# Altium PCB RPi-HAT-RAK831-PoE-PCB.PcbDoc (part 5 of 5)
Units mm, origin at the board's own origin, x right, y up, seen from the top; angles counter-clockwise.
Board outline 65 x 56 mm, 2 copper layers (Top Layer, Bottom Layer); 9 components, 14 nets, 9110 pads, 249 vias.
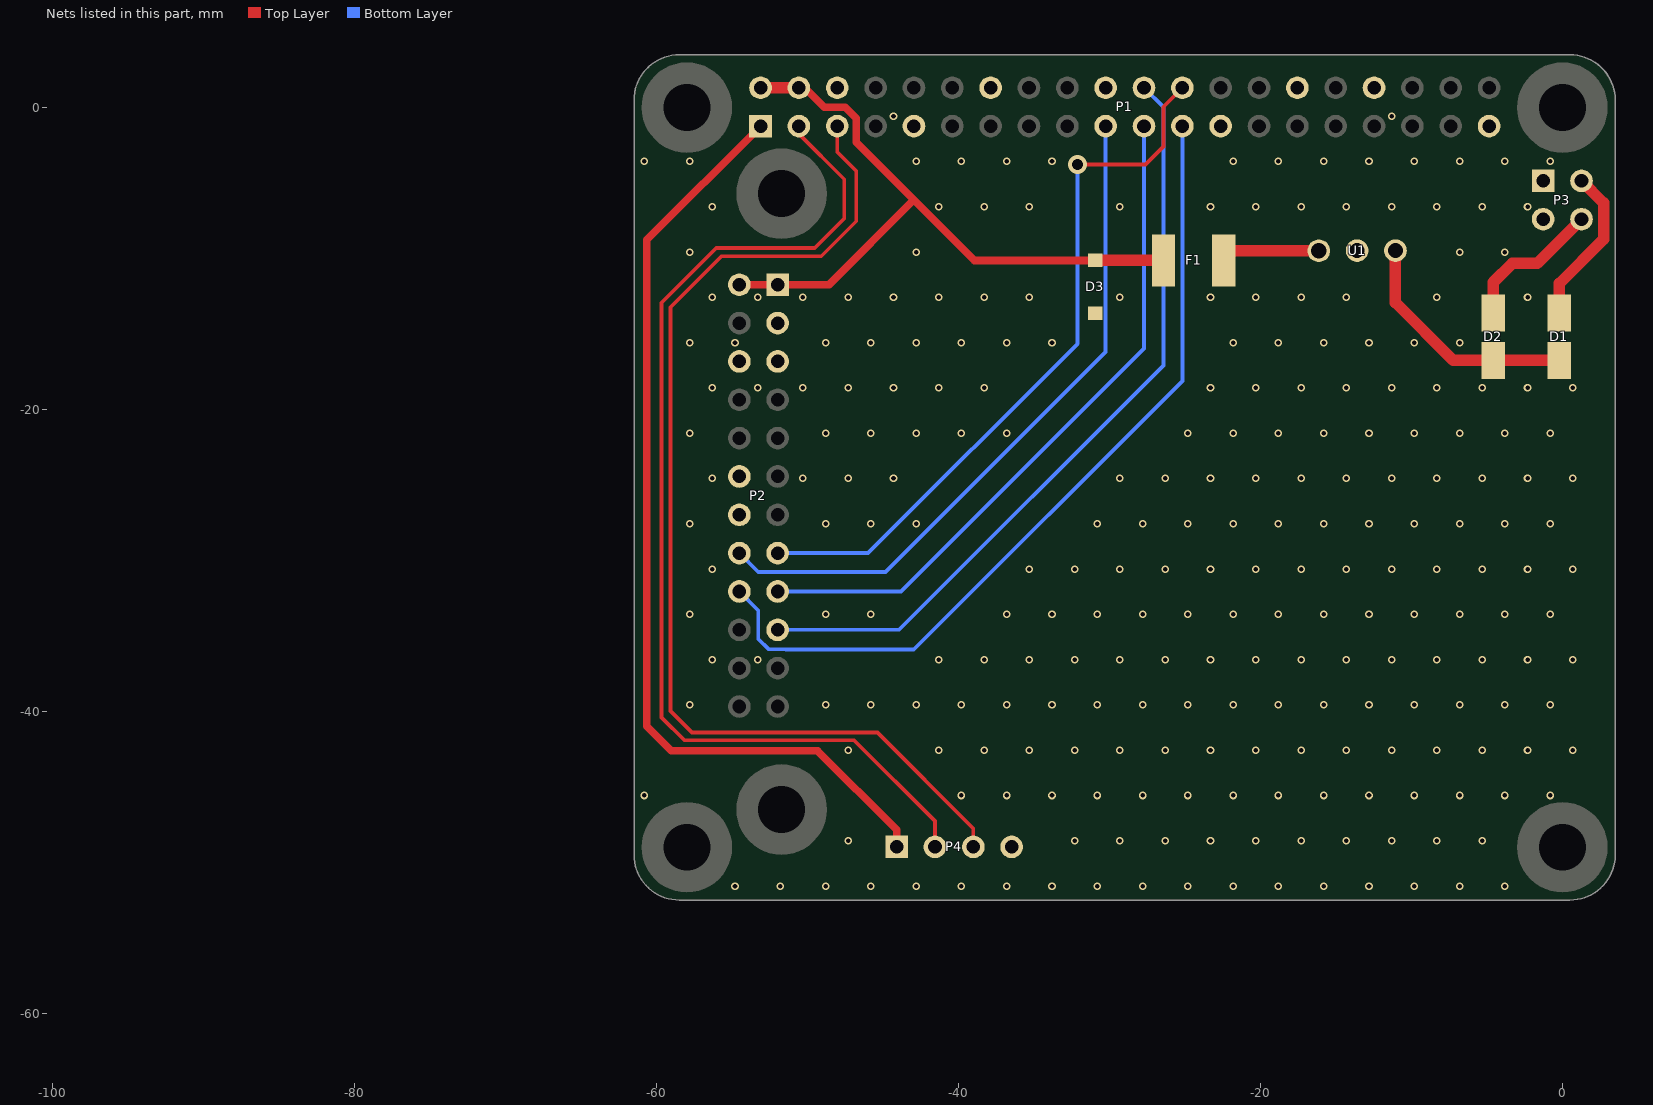
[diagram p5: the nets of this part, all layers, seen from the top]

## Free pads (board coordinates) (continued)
  round 0.025 on Top Overlay: 1(-16.322,-45.815) 1(-16.322,-45.79) 1(-16.322,-45.764) 1(-16.322,-44.621) 1(-16.322,-44.596) 1(-16.322,-44.571) 1(-16.297,-45.866) 1(-16.297,-45.841) 1(-16.297,-44.545) 1(-16.297,-44.52) 1(-16.297,-44.494) 1(-16.271,-45.917) 1(-16.271,-45.891) 1(-16.271,-44.469) 1(-16.271,-44.444) 1(-16.246,-45.968) 1(-16.246,-45.942) 1(-16.246,-44.418) 1(-16.22,-45.993) 1(-16.22,-44.393) 1(-16.22,-44.367) 1(-16.195,-46.044) 1(-16.195,-46.018) 1(-16.195,-44.342) 1(-16.195,-44.317) 1(-16.17,-46.069) 1(-16.17,-44.291) 1(-16.144,-46.095) 1(-16.144,-44.266) 1(-16.144,-44.24) 1(-16.119,-46.145) 1(-16.119,-46.12) 1(-16.119,-44.215) 1(-16.093,-46.171) 1(-16.093,-44.19) 1(-16.068,-46.196) 1(-16.068,-44.164) 1(-16.043,-46.222) 1(-16.043,-44.139) 1(-16.017,-46.247) 1(-16.017,-44.113) 1(-15.992,-44.088) 1(-15.966,-46.272) 1(-15.966,-44.063) 1(-15.941,-46.298) 1(-15.941,-44.037) 1(-15.916,-46.323) 1(-15.916,-44.012) 1(-15.89,-43.986) 1(-15.865,-46.349) 1(-15.839,-46.374) 1(-15.839,-43.961) 1(-15.814,-43.936) 1(-15.789,-46.399) 1(-15.763,-43.91) 1(-15.738,-46.425) 1(-15.738,-43.885) 1(-15.687,-46.45) 1(-15.687,-43.859) 1(-15.636,-43.834) 1(-15.611,-46.476) 1(-15.585,-45.51) 1(-15.585,-45.485) 1(-15.585,-45.46) 1(-15.585,-45.434) 1(-15.585,-45.409) 1(-15.585,-44.875) 1(-15.585,-44.85) 1(-15.585,-44.825) 1(-15.585,-44.799) 1(-15.56,-45.612) 1(-15.56,-45.587) 1(-15.56,-45.561) 1(-15.56,-45.536) 1(-15.56,-44.774) 1(-15.56,-44.748) 1(-15.56,-44.723) 1(-15.56,-44.698) 1(-15.56,-43.809) 1(-15.535,-46.501) 1(-15.535,-45.663) 1(-15.535,-45.637) 1(-15.535,-44.672) 1(-15.535,-44.647) 1(-15.509,-45.714) 1(-15.509,-45.688) 1(-15.509,-44.621) 1(-15.509,-44.596) 1(-15.484,-45.764) 1(-15.484,-45.739) 1(-15.484,-44.571) 1(-15.484,-44.545) 1(-15.484,-43.783) 1(-15.458,-45.79) 1(-15.458,-44.52) 1(-15.458,-44.494) 1(-15.433,-46.526) 1(-15.433,-45.815) 1(-15.433,-44.469) 1(-15.408,-45.841) 1(-15.408,-44.444) 1(-15.408,-43.758) 1(-15.382,-45.866) 1(-15.382,-44.418) 1(-15.357,-45.891) 1(-15.357,-44.393) 1(-15.331,-44.367) 1(-15.306,-45.917) 1(-15.306,-44.342) 1(-15.281,-46.552) 1(-15.281,-45.942) 1(-15.255,-44.317) 1(-15.255,-43.732) 1(-15.204,-45.968) 1(-15.204,-44.291) 1(-15.128,-45.993) 1(-15.128,-44.266) 1(-15.001,-46.018) 1(-14.95,-44.266) 1(-14.849,-44.291) 1(-14.823,-43.732) 1(-14.798,-44.317) 1(-14.773,-44.342) 1(-14.747,-44.367) 1(-14.722,-46.552) 1(-14.722,-44.393) 1(-14.696,-44.418) 1(-14.671,-44.469) 1(-14.671,-44.444) 1(-14.671,-43.758) 1(-14.646,-46.018) 1(-14.646,-44.52) 1(-14.646,-44.494) 1(-14.62,-44.596) 1(-14.62,-44.571) 1(-14.62,-44.545) 1(-14.595,-44.723) 1(-14.595,-44.698) 1(-14.595,-44.672) 1(-14.595,-44.647) 1(-14.595,-44.621) 1(-14.569,-44.875) 1(-14.569,-44.85) 1(-14.569,-44.825) 1(-14.569,-44.799) 1(-14.569,-44.774) 1(-14.569,-44.748) 1(-14.569,-43.783) 1(-14.519,-46.526) 1(-14.519,-45.993) 1(-14.519,-43.809) 1(-14.442,-43.834) 1(-14.417,-45.968) 1(-14.392,-46.501) 1(-14.392,-43.859) 1(-14.341,-45.942) 1(-14.341,-43.885) 1(-14.315,-43.91) 1(-14.29,-46.476) 1(-14.265,-45.917) 1(-14.265,-43.936) 1(-14.239,-43.961) 1(-14.214,-46.45) 1(-14.214,-45.891) 1(-14.214,-43.986) 1(-14.188,-44.012) 1(-14.163,-46.425) 1(-14.163,-45.866) 1(-14.163,-44.037) 1(-14.138,-44.063) 1(-14.112,-45.841) 1(-14.112,-44.088) 1(-14.087,-46.399) 1(-14.087,-45.815) 1(-14.087,-44.113) 1(-14.061,-44.139) 1(-14.036,-46.374) 1(-14.036,-46.349) 1(-14.036,-46.323) 1(-14.036,-46.298) 1(-14.036,-46.272) 1(-14.036,-46.247) 1(-14.036,-46.222) 1(-14.036,-46.196) 1(-14.036,-46.171) 1(-14.036,-46.145) 1(-14.036,-46.12) 1(-14.036,-46.095) 1(-14.036,-46.069) 1(-14.036,-46.044) 1(-14.036,-46.018) 1(-14.036,-45.993) 1(-14.036,-45.968) 1(-14.036,-45.942) 1(-14.036,-45.917) 1(-14.036,-45.891) 1(-14.036,-45.866) 1(-14.036,-45.841) 1(-14.036,-45.815) 1(-14.036,-44.19) 1(-14.036,-44.164) 1(-14.011,-44.215) 1(-13.985,-44.266) 1(-13.985,-44.24) 1(-13.96,-44.317) 1(-13.96,-44.291) 1(-13.934,-44.367) 1(-13.934,-44.342) 1(-13.909,-44.418) 1(-13.909,-44.393) 1(-13.884,-44.494) 1(-13.884,-44.469) 1(-13.884,-44.444) 1(-13.858,-44.571) 1(-13.858,-44.545) 1(-13.858,-44.52) 1(-13.833,-44.698) 1(-13.833,-44.672) 1(-13.833,-44.647) 1(-13.833,-44.621) 1(-13.833,-44.596) 1(-13.807,-44.901) 1(-13.807,-44.875) 1(-13.807,-44.85) 1(-13.807,-44.825) 1(-13.807,-44.799) 1(-13.807,-44.774) 1(-13.807,-44.748) 1(-13.807,-44.723) 1(-13.782,-45.383) 1(-13.782,-45.358) 1(-13.782,-45.333) 1(-13.782,-45.307) 1(-13.782,-45.282) 1(-13.782,-45.256) 1(-13.782,-45.231) 1(-13.782,-45.206) 1(-13.782,-45.18) 1(-13.782,-45.155) 1(-13.782,-45.129) 1(-13.782,-45.104) 1(-13.782,-45.079) 1(-13.782,-45.053) 1(-13.782,-45.028) 1(-13.782,-45.002) 1(-13.782,-44.977) 1(-13.782,-44.952) 1(-13.782,-44.926) 1(-13.63,-43.834) 1(-13.63,-43.809) 1(-13.63,-43.783) 1(-13.604,-43.91) 1(-13.604,-43.885) 1(-13.604,-43.859) 1(-13.579,-44.012) 1(-13.579,-43.986) 1(-13.579,-43.961) 1(-13.579,-43.936) 1(-13.553,-44.088) 1(-13.553,-44.063) 1(-13.553,-44.037) 1(-13.528,-44.19) 1(-13.528,-44.164) 1(-13.528,-44.139) 1(-13.528,-44.113) 1(-13.503,-44.266) 1(-13.503,-44.24) 1(-13.503,-44.215) 1(-13.477,-44.367) 1(-13.477,-44.342) 1(-13.477,-44.317) 1(-13.477,-44.291) 1(-13.452,-44.444) 1(-13.452,-44.418) 1(-13.452,-44.393) 1(-13.426,-44.545) 1(-13.426,-44.52) 1(-13.426,-44.494) 1(-13.426,-44.469) 1(-13.401,-44.621) 1(-13.401,-44.596) 1(-13.401,-44.571) 1(-13.376,-44.723) 1(-13.376,-44.698) 1(-13.376,-44.672) 1(-13.376,-44.647) 1(-13.35,-44.799) 1(-13.35,-44.774) 1(-13.35,-44.748) 1(-13.325,-44.901) 1(-13.325,-44.875) 1(-13.325,-44.85) 1(-13.325,-44.825) 1(-13.299,-44.977) 1(-13.299,-44.952) 1(-13.299,-44.926) 1(-13.274,-45.079) 1(-13.274,-45.053) 1(-13.274,-45.028) 1(-13.274,-45.002) 1(-13.249,-45.155) 1(-13.249,-45.129) 1(-13.249,-45.104) 1(-13.223,-45.256) 1(-13.223,-45.231) 1(-13.223,-45.206) 1(-13.223,-45.18) 1(-13.198,-45.333) 1(-13.198,-45.307) 1(-13.198,-45.282) 1(-13.172,-45.434) 1(-13.172,-45.409) 1(-13.172,-45.383) 1(-13.172,-45.358) 1(-13.147,-45.51) 1(-13.147,-45.485) 1(-13.147,-45.46) 1(-13.122,-45.612) 1(-13.122,-45.587) 1(-13.122,-45.561) 1(-13.122,-45.536) 1(-13.096,-45.688) 1(-13.096,-45.663) 1(-13.096,-45.637) 1(-13.071,-45.79) 1(-13.071,-45.764) 1(-13.071,-45.739) 1(-13.071,-45.714) 1(-13.045,-45.866) 1(-13.045,-45.841) 1(-13.045,-45.815) 1(-13.02,-45.942) 1(-13.02,-45.917) 1(-13.02,-45.891) 1(-12.995,-46.044) 1(-12.995,-46.018) 1(-12.995,-45.993) 1(-12.995,-45.968) 1(-12.969,-46.12) 1(-12.969,-46.095) 1(-12.969,-46.069) 1(-12.944,-46.222) 1(-12.944,-46.196) 1(-12.944,-46.171) 1(-12.944,-46.145) 1(-12.918,-46.298) 1(-12.918,-46.272) 1(-12.918,-46.247) 1(-12.893,-46.399) 1(-12.893,-46.374) 1(-12.893,-46.349) 1(-12.893,-46.323) 1(-12.868,-46.476) 1(-12.868,-46.45) 1(-12.868,-46.425) 1(-12.842,-46.501) 1(-12.766,-43.885) 1(-12.766,-43.859) 1(-12.766,-43.834) 1(-12.766,-43.809) 1(-12.766,-43.783) 1(-12.741,-43.986) 1(-12.741,-43.961) 1(-12.741,-43.936) 1(-12.741,-43.91) 1(-12.715,-44.113) 1(-12.715,-44.088) 1(-12.715,-44.063) 1(-12.715,-44.037) 1(-12.715,-44.012) 1(-12.69,-44.215) 1(-12.69,-44.19) 1(-12.69,-44.164) 1(-12.69,-44.139) 1(-12.664,-44.342) 1(-12.664,-44.317) 1(-12.664,-44.291) 1(-12.664,-44.266) 1(-12.664,-44.24) 1(-12.639,-44.444) 1(-12.639,-44.418) 1(-12.639,-44.393) 1(-12.639,-44.367) 1(-12.614,-44.571) 1(-12.614,-44.545) 1(-12.614,-44.52) 1(-12.614,-44.494) 1(-12.614,-44.469) 1(-12.588,-44.672) 1(-12.588,-44.647) 1(-12.588,-44.621) 1(-12.588,-44.596) 1(-12.563,-44.799) 1(-12.563,-44.774) 1(-12.563,-44.748) 1(-12.563,-44.723) 1(-12.563,-44.698) 1(-12.537,-44.901) 1(-12.537,-44.875) 1(-12.537,-44.85) 1(-12.537,-44.825) 1(-12.512,-45.028) 1(-12.512,-45.002) 1(-12.512,-44.977) 1(-12.512,-44.952) 1(-12.512,-44.926) 1(-12.487,-45.129) 1(-12.487,-45.104) 1(-12.487,-45.079) 1(-12.487,-45.053) 1(-12.461,-45.231) 1(-12.461,-45.206) 1(-12.461,-45.18) 1(-12.461,-45.155) 1(-12.436,-45.358) 1(-12.436,-45.333) 1(-12.436,-45.307) 1(-12.436,-45.282) 1(-12.436,-45.256) 1(-12.41,-45.46) 1(-12.41,-45.434) 1(-12.41,-45.409) 1(-12.41,-45.383) 1(-12.385,-45.587) 1(-12.385,-45.561) 1(-12.385,-45.536) 1(-12.385,-45.51) 1(-12.385,-45.485) 1(-12.36,-45.739) 1(-12.36,-45.714) 1(-12.36,-45.688) 1(-12.36,-45.663) 1(-12.36,-45.637) 1(-12.36,-45.612) 1(-12.334,-45.739) 1(-12.334,-45.714) 1(-12.334,-45.688) 1(-12.334,-45.663) 1(-12.334,-45.637) 1(-12.309,-45.612) 1(-12.309,-45.587) 1(-12.309,-45.561) 1(-12.309,-45.536) 1(-12.283,-45.51) 1(-12.283,-45.485) 1(-12.283,-45.46) 1(-12.283,-45.434) 1(-12.258,-45.409) 1(-12.258,-45.383) 1(-12.258,-45.358) 1(-12.233,-45.333) 1(-12.233,-45.307) 1(-12.233,-45.282) 1(-12.233,-45.256) 1(-12.207,-45.231) 1(-12.207,-45.206) 1(-12.207,-45.18) 1(-12.207,-45.155) 1(-12.182,-45.129) 1(-12.182,-45.104) 1(-12.182,-45.079) 1(-12.156,-45.053) 1(-12.156,-45.028) 1(-12.156,-45.002) 1(-12.156,-44.977) 1(-12.131,-44.952) 1(-12.131,-44.926) 1(-12.131,-44.901) 1(-12.131,-44.875) 1(-12.106,-44.85) 1(-12.106,-44.825) 1(-12.106,-44.799) 1(-12.08,-44.774) 1(-12.08,-44.748) 1(-12.08,-44.723) 1(-12.08,-44.698) 1(-12.055,-44.672) 1(-12.055,-44.647) 1(-12.055,-44.621) 1(-12.055,-44.596) 1(-12.029,-44.571) 1(-12.029,-44.545) 1(-12.029,-44.52) 1(-12.004,-44.494) 1(-12.004,-44.469) 1(-12.004,-44.444) 1(-12.004,-44.418) 1(-11.979,-46.501) 1(-11.979,-46.476) 1(-11.979,-44.393) 1(-11.979,-44.367) 1(-11.979,-44.342) 1(-11.979,-44.317) 1(-11.953,-46.45) 1(-11.953,-46.425) 1(-11.953,-46.399) 1(-11.953,-46.374) 1(-11.953,-44.291) 1(-11.953,-44.266) 1(-11.953,-44.24) 1(-11.928,-46.349) 1(-11.928,-46.323) 1(-11.928,-46.298) 1(-11.928,-44.215) 1(-11.928,-44.19) 1(-11.928,-44.164) 1(-11.928,-44.139) 1(-11.902,-46.272) 1(-11.902,-46.247) 1(-11.902,-46.222) 1(-11.902,-46.196) 1(-11.902,-44.113) 1(-11.902,-44.088) 1(-11.902,-44.063) 1(-11.902,-44.037) 1(-11.877,-46.171) 1(-11.877,-46.145) 1(-11.877,-46.12) 1(-11.877,-46.095) 1(-11.877,-44.012) 1(-11.877,-43.986) 1(-11.877,-43.961) 1(-11.852,-46.069) 1(-11.852,-46.044) 1(-11.852,-46.018) 1(-11.852,-43.936) 1(-11.852,-43.91) 1(-11.852,-43.885) 1(-11.852,-43.859) 1(-11.826,-45.993) 1(-11.826,-45.968) 1(-11.826,-45.942) 1(-11.826,-45.917) 1(-11.826,-43.834) 1(-11.826,-43.809) 1(-11.826,-43.783) 1(-11.801,-45.891) 1(-11.801,-45.866) 1(-11.801,-45.841) 1(-11.801,-45.815) 1(-11.775,-45.79) 1(-11.775,-45.764) 1(-11.775,-45.739) 1(-11.75,-45.714) 1(-11.75,-45.688) 1(-11.75,-45.663) 1(-11.75,-45.637) 1(-11.725,-45.612) 1(-11.725,-45.587) 1(-11.725,-45.561) 1(-11.725,-45.536) 1(-11.699,-45.51) 1(-11.699,-45.485) 1(-11.699,-45.46) 1(-11.674,-45.434) 1(-11.674,-45.409) 1(-11.674,-45.383) 1(-11.674,-45.358) 1(-11.648,-45.333) 1(-11.648,-45.307) 1(-11.648,-45.282) 1(-11.648,-45.256) 1(-11.623,-45.231) 1(-11.623,-45.206) 1(-11.623,-45.18) 1(-11.598,-45.155) 1(-11.598,-45.129) 1(-11.598,-45.104) 1(-11.598,-45.079) 1(-11.572,-45.053) 1(-11.572,-45.028) 1(-11.572,-45.002) 1(-11.572,-44.977) 1(-11.547,-44.952) 1(-11.547,-44.926) 1(-11.547,-44.901) 1(-11.521,-44.875) 1(-11.521,-44.85) 1(-11.521,-44.825) 1(-11.521,-44.799) 1(-11.521,-44.774) 1(-11.496,-44.748) 1(-11.496,-44.723) 1(-11.496,-44.698) 1(-11.471,-44.825) 1(-11.471,-44.799) 1(-11.471,-44.774) 1(-11.471,-44.748) 1(-11.471,-44.723) 1(-11.471,-44.698) 1(-11.445,-44.926) 1(-11.445,-44.901) 1(-11.445,-44.875) 1(-11.445,-44.85) 1(-11.42,-45.028) 1(-11.42,-45.002) 1(-11.42,-44.977) 1(-11.42,-44.952) 1(-11.394,-45.129) 1(-11.394,-45.104) 1(-11.394,-45.079) 1(-11.394,-45.053) 1(-11.369,-45.231) 1(-11.369,-45.206) 1(-11.369,-45.18) 1(-11.369,-45.155) 1(-11.344,-45.333) 1(-11.344,-45.307) 1(-11.344,-45.282) 1(-11.344,-45.256) 1(-11.318,-45.409) 1(-11.318,-45.383) 1(-11.318,-45.358) 1(-11.293,-45.51) 1(-11.293,-45.485) 1(-11.293,-45.46) 1(-11.293,-45.434) 1(-11.267,-45.612) 1(-11.267,-45.587) 1(-11.267,-45.561) 1(-11.267,-45.536) 1(-11.242,-45.714) 1(-11.242,-45.688) 1(-11.242,-45.663) 1(-11.242,-45.637) 1(-11.217,-45.815) 1(-11.217,-45.79) 1(-11.217,-45.764) 1(-11.217,-45.739) 1(-11.191,-45.917) 1(-11.191,-45.891) 1(-11.191,-45.866) 1(-11.191,-45.841) 1(-11.166,-46.018) 1(-11.166,-45.993) 1(-11.166,-45.968) 1(-11.166,-45.942) 1(-11.14,-46.12) 1(-11.14,-46.095) 1(-11.14,-46.069) 1(-11.14,-46.044) 1(-11.115,-46.222) 1(-11.115,-46.196) 1(-11.115,-46.171) 1(-11.115,-46.145) 1(-11.09,-46.323) 1(-11.09,-46.298) 1(-11.09,-46.272) 1(-11.09,-46.247) 1(-11.064,-46.425) 1(-11.064,-46.399) 1(-11.064,-46.374) 1(-11.064,-46.349) 1(-11.039,-46.501) 1(-11.039,-46.476) 1(-11.039,-46.45) 1(-11.013,-43.834) 1(-11.013,-43.809) 1(-11.013,-43.783) 1(-10.988,-43.961) 1(-10.988,-43.936) 1(-10.988,-43.91) 1(-10.988,-43.885) 1(-10.988,-43.859) 1(-10.963,-44.063) 1(-10.963,-44.037) 1(-10.963,-44.012) 1(-10.963,-43.986) 1(-10.937,-44.164) 1(-10.937,-44.139) 1(-10.937,-44.113) 1(-10.937,-44.088) 1(-10.912,-44.266) 1(-10.912,-44.24) 1(-10.912,-44.215) 1(-10.912,-44.19) 1(-10.886,-44.367) 1(-10.886,-44.342) 1(-10.886,-44.317) 1(-10.886,-44.291) 1(-10.861,-44.469) 1(-10.861,-44.444) 1(-10.861,-44.418) 1(-10.861,-44.393) 1(-10.836,-44.571) 1(-10.836,-44.545) 1(-10.836,-44.52) 1(-10.836,-44.494) 1(-10.81,-44.672) 1(-10.81,-44.647) 1(-10.81,-44.621) 1(-10.81,-44.596) 1(-10.785,-44.799) 1(-10.785,-44.774) 1(-10.785,-44.748) 1(-10.785,-44.723) 1(-10.785,-44.698) 1(-10.759,-44.901) 1(-10.759,-44.875) 1(-10.759,-44.85) 1(-10.759,-44.825) 1(-10.734,-45.002) 1(-10.734,-44.977) 1(-10.734,-44.952) 1(-10.734,-44.926) 1(-10.709,-45.104) 1(-10.709,-45.079) 1(-10.709,-45.053) 1(-10.709,-45.028) 1(-10.683,-45.206) 1(-10.683,-45.18) 1(-10.683,-45.155) 1(-10.683,-45.129) 1(-10.658,-45.307) 1(-10.658,-45.282) 1(-10.658,-45.256) 1(-10.658,-45.231) 1(-10.632,-45.409) 1(-10.632,-45.383) 1(-10.632,-45.358) 1(-10.632,-45.333) 1(-10.607,-45.536) 1(-10.607,-45.51) 1(-10.607,-45.485) 1(-10.607,-45.46) 1(-10.607,-45.434) 1(-10.582,-45.663) 1(-10.582,-45.637) 1(-10.582,-45.612) 1(-10.582,-45.587) 1(-10.582,-45.561) 1(-10.556,-45.688) 1(-10.531,-45.688) 1(-10.531,-45.663) 1(-10.531,-45.637) 1(-10.531,-45.612) 1(-10.531,-45.587) 1(-10.505,-45.561) 1(-10.505,-45.536) 1(-10.505,-45.51) 1(-10.505,-45.485) 1(-10.505,-45.46) 1(-10.48,-45.434) 1(-10.48,-45.409) 1(-10.48,-45.383) 1(-10.48,-45.358) 1(-10.48,-45.333) 1(-10.455,-45.307) 1(-10.455,-45.282) 1(-10.455,-45.256) 1(-10.455,-45.231) 1(-10.455,-45.206) 1(-10.429,-45.18) 1(-10.429,-45.155) 1(-10.429,-45.129) 1(-10.429,-45.104) 1(-10.404,-45.079) 1(-10.404,-45.053) 1(-10.404,-45.028) 1(-10.404,-45.002) 1(-10.404,-44.977) 1(-10.378,-44.952) 1(-10.378,-44.926) 1(-10.378,-44.901) 1(-10.378,-44.875) 1(-10.378,-44.85) 1(-10.353,-44.825) 1(-10.353,-44.799) 1(-10.353,-44.774) 1(-10.353,-44.748) 1(-10.353,-44.723) 1(-10.328,-44.698) 1(-10.328,-44.672) 1(-10.328,-44.647) 1(-10.328,-44.621) 1(-10.302,-44.596) 1(-10.302,-44.571) 1(-10.302,-44.545) 1(-10.302,-44.52) 1(-10.302,-44.494) 1(-10.277,-44.469) 1(-10.277,-44.444) 1(-10.277,-44.418) 1(-10.277,-44.393) 1(-10.277,-44.367) 1(-10.251,-44.342) 1(-10.251,-44.317) 1(-10.251,-44.291) 1(-10.251,-44.266) 1(-10.251,-44.24) 1(-10.226,-44.215) 1(-10.226,-44.19) 1(-10.226,-44.164) 1(-10.226,-44.139) 1(-10.201,-44.113) 1(-10.201,-44.088) 1(-10.201,-44.063) 1(-10.201,-44.037) 1(-10.201,-44.012) 1(-10.175,-43.986) 1(-10.175,-43.961) 1(-10.175,-43.936) 1(-10.175,-43.91) 1(-10.175,-43.885) 1(-10.15,-46.501) 1(-10.15,-46.476) 1(-10.15,-43.859) 1(-10.15,-43.834) 1(-10.15,-43.809) 1(-10.15,-43.783) 1(-10.124,-46.45) 1(-10.124,-46.425) 1(-10.124,-46.399) 1(-10.099,-46.374) 1(-10.099,-46.349) 1(-10.099,-46.323) 1(-10.099,-46.298) 1(-10.074,-46.272) 1(-10.074,-46.247) 1(-10.074,-46.222) 1(-10.048,-46.196) 1(-10.048,-46.171) 1(-10.048,-46.145) 1(-10.048,-46.12) 1(-10.023,-46.095) 1(-10.023,-46.069) 1(-10.023,-46.044) 1(-9.997,-46.018) 1(-9.997,-45.993) 1(-9.997,-45.968) 1(-9.997,-45.942) 1(-9.972,-45.917) 1(-9.972,-45.891) 1(-9.972,-45.866) 1(-9.947,-45.841) 1(-9.947,-45.815) 1(-9.947,-45.79) 1(-9.947,-45.764) 1(-9.921,-45.739) 1(-9.921,-45.714) 1(-9.921,-45.688) 1(-9.896,-45.663) 1(-9.896,-45.637) 1(-9.896,-45.612) 1(-9.896,-45.587) 1(-9.87,-45.561) 1(-9.87,-45.536) 1(-9.87,-45.51) 1(-9.845,-45.485) 1(-9.845,-45.46) 1(-9.845,-45.434) 1(-9.82,-45.409) 1(-9.82,-45.383) 1(-9.82,-45.358) 1(-9.82,-45.333) 1(-9.794,-45.307) 1(-9.794,-45.282) 1(-9.794,-45.256) 1(-9.769,-45.231) 1(-9.769,-45.206) 1(-9.769,-45.18) 1(-9.769,-45.155) 1(-9.743,-45.129) 1(-9.743,-45.104) 1(-9.743,-45.079) 1(-9.718,-45.053) 1(-9.718,-45.028) 1(-9.718,-45.002) 1(-9.718,-44.977) 1(-9.693,-44.952) 1(-9.693,-44.926) 1(-9.693,-44.901) 1(-9.667,-44.875) 1(-9.667,-44.85) 1(-9.667,-44.825) 1(-9.667,-44.799) 1(-9.642,-44.774) 1(-9.642,-44.748) 1(-9.642,-44.723) 1(-9.616,-44.698) 1(-9.616,-44.672) 1(-9.616,-44.647) 1(-9.616,-44.621) 1(-9.591,-44.596) 1(-9.591,-44.571) 1(-9.591,-44.545) 1(-9.566,-44.52) 1(-9.566,-44.494) 1(-9.566,-44.469) 1(-9.566,-44.444) 1(-9.54,-44.418) 1(-9.54,-44.393) 1(-9.54,-44.367) 1(-9.515,-44.342) 1(-9.515,-44.317) 1(-9.515,-44.291) 1(-9.489,-44.266) 1(-9.489,-44.24) 1(-9.489,-44.215) 1(-9.489,-44.19) 1(-9.464,-44.164) 1(-9.464,-44.139) 1(-9.464,-44.113) 1(-9.439,-44.088) 1(-9.439,-44.063) 1(-9.439,-44.037) 1(-9.439,-44.012) 1(-9.413,-43.986) 1(-9.413,-43.961) 1(-9.413,-43.936) 1(-9.388,-43.91) 1(-9.388,-43.885) 1(-9.388,-43.859) 1(-9.388,-43.834) 1(-9.362,-43.809) 1(-9.362,-43.783) 1(-9.185,-45.942) 1(-9.185,-45.917) 1(-9.185,-45.891) 1(-9.185,-45.866) 1(-9.185,-45.841) 1(-9.185,-45.815) 1(-9.185,-45.79) 1(-9.185,-45.764) 1(-9.185,-45.739) 1(-9.185,-45.714) 1(-9.185,-45.688) 1(-9.185,-45.663) 1(-9.185,-45.637) 1(-9.185,-45.612) 1(-9.185,-45.587) 1(-9.185,-45.561) 1(-9.185,-45.536) 1(-9.159,-46.044) 1(-9.159,-46.018) 1(-9.159,-45.993) 1(-9.159,-45.968) 1(-9.159,-45.51) 1(-9.159,-45.485) 1(-9.159,-45.46) 1(-9.134,-46.095) 1(-9.134,-46.069) 1(-9.134,-45.434) 1(-9.134,-45.409) 1(-9.134,-45.383) 1(-9.108,-46.145) 1(-9.108,-46.12) 1(-9.108,-45.358) 1(-9.108,-45.333) 1(-9.083,-46.196) 1(-9.083,-46.171) 1(-9.083,-45.307) 1(-9.083,-45.282) 1(-9.058,-46.222) 1(-9.058,-45.256) 1(-9.032,-46.272) 1(-9.032,-46.247) 1(-9.032,-45.231) 1(-9.032,-45.206) 1(-9.007,-46.298) 1(-9.007,-45.18) 1(-8.981,-46.323) 1(-8.981,-45.155) 1(-8.956,-46.349) 1(-8.956,-45.129) 1(-8.931,-46.374) 1(-8.931,-45.104) 1(-8.931,-44.545) 1(-8.931,-44.52) 1(-8.931,-44.494) 1(-8.931,-44.469) 1(-8.931,-44.444) 1(-8.931,-44.418) 1(-8.931,-44.393) 1(-8.931,-44.367) 1(-8.931,-44.342) 1(-8.931,-44.317) 1(-8.931,-44.291) 1(-8.931,-44.266) 1(-8.931,-44.24) 1(-8.931,-44.215) 1(-8.931,-44.19) 1(-8.931,-44.164) 1(-8.931,-44.139) 1(-8.931,-44.113) 1(-8.931,-44.088) 1(-8.931,-44.063) 1(-8.931,-44.037) 1(-8.931,-44.012) 1(-8.931,-43.986) 1(-8.931,-43.961) 1(-8.905,-45.079) 1(-8.905,-43.936) 1(-8.88,-46.399) 1(-8.854,-46.425) 1(-8.854,-45.053) 1(-8.854,-44.545) 1(-8.854,-43.91) 1(-8.829,-45.028) 1(-8.829,-44.52) 1(-8.804,-46.45) 1(-8.778,-46.476) 1(-8.778,-45.002) 1(-8.778,-44.494) 1(-8.778,-43.885) 1(-8.753,-44.469) 1(-8.727,-44.977) 1(-8.702,-46.501) 1(-8.702,-44.444) 1(-8.702,-43.859) 1(-8.677,-44.952) 1(-8.651,-44.418) 1(-8.626,-46.526) 1(-8.626,-44.926) 1(-8.626,-43.834) 1(-8.6,-44.393) 1(-8.55,-44.901) 1(-8.55,-44.367) 1(-8.524,-43.809) 1(-8.499,-46.552) 1(-8.473,-44.342) 1(-8.448,-44.875) 1(-8.423,-45.714) 1(-8.423,-45.688) 1(-8.423,-45.663) 1(-8.423,-45.637) 1(-8.423,-43.783) 1(-8.397,-45.815) 1(-8.397,-45.79) 1(-8.397,-45.764) 1(-8.397,-45.739) 1(-8.397,-45.612) 1(-8.397,-45.587) 1(-8.397,-45.561) 1(-8.397,-45.536) 1(-8.397,-44.317) 1(-8.372,-45.866) 1(-8.372,-45.841) 1(-8.372,-45.51) 1(-8.372,-45.485) 1(-8.346,-45.891) 1(-8.346,-45.46) 1(-8.346,-45.434) 1(-8.321,-45.917) 1(-8.321,-45.409) 1(-8.321,-44.85) 1(-8.296,-45.942) 1(-8.296,-45.383) 1(-8.296,-44.291) 1(-8.296,-43.758) 1(-8.27,-45.968) 1(-8.245,-45.358) 1(-8.219,-45.993) 1(-8.194,-45.333) 1(-8.143,-46.018) 1(-8.143,-45.307) 1(-8.143,-44.825) 1(-8.143,-44.266) 1(-8.118,-46.552) 1(-8.118,-43.732) 1(-8.042,-45.282) 1(-7.991,-46.526) 1(-7.965,-44.799) 1(-7.94,-46.018) 1(-7.915,-46.501) 1(-7.864,-46.476) 1(-7.864,-45.256) 1(-7.838,-45.993) 1(-7.838,-44.266) 1(-7.813,-46.45) 1(-7.788,-45.968) 1(-7.788,-44.774) 1(-7.762,-46.425) 1(-7.762,-45.942) 1(-7.762,-44.291) 1(-7.737,-46.399) 1(-7.711,-46.374) 1(-7.711,-45.917) 1(-7.686,-45.891) 1(-7.686,-45.231) 1(-7.686,-44.317) 1(-7.661,-46.349) 1(-7.661,-45.866) 1(-7.661,-44.342) 1(-7.635,-46.323) 1(-7.635,-45.841) 1(-7.635,-44.367) 1(-7.635,-43.732) 1(-7.61,-46.298) 1(-7.61,-45.815) 1(-7.61,-45.79) 1(-7.61,-44.393) 1(-7.584,-46.272) 1(-7.584,-45.764) 1(-7.584,-44.748) 1(-7.584,-44.418) 1(-7.559,-46.247) 1(-7.559,-46.222) 1(-7.559,-45.739) 1(-7.559,-45.714) 1(-7.559,-45.688) 1(-7.559,-44.469) 1(-7.559,-44.444) 1(-7.534,-46.196) 1(-7.534,-45.663) 1(-7.534,-45.637) 1(-7.534,-44.52) 1(-7.534,-44.494) 1(-7.508,-46.501) 1(-7.508,-46.476) 1(-7.508,-46.45) 1(-7.508,-46.425) 1(-7.508,-46.399) 1(-7.508,-46.374) 1(-7.508,-46.349) 1(-7.508,-46.323) 1(-7.508,-46.298) 1(-7.508,-46.272) 1(-7.508,-46.247) 1(-7.508,-46.222) 1(-7.508,-46.196) 1(-7.508,-45.612) 1(-7.508,-45.587) 1(-7.508,-45.561) 1(-7.508,-45.536) 1(-7.508,-45.51) 1(-7.508,-45.485) 1(-7.508,-44.647) 1(-7.508,-44.621) 1(-7.508,-44.596) 1(-7.508,-44.571) 1(-7.508,-44.545) 1(-7.483,-45.46) 1(-7.483,-45.434) 1(-7.483,-45.409) 1(-7.483,-45.383) 1(-7.483,-45.358) 1(-7.483,-45.333) 1(-7.483,-45.307) 1(-7.483,-45.282) 1(-7.483,-45.256) 1(-7.483,-45.231) 1(-7.483,-44.723) 1(-7.483,-44.698) 1(-7.483,-44.672) 1(-7.483,-43.758) 1(-7.381,-43.783) 1(-7.305,-43.809) 1(-7.229,-43.834) 1(-7.178,-43.859) 1(-7.153,-43.885) 1(-7.102,-43.91) 1(-7.076,-43.936) 1(-7.026,-43.961) 1(-7,-43.986) 1(-6.975,-44.012) 1(-6.949,-44.037) 1(-6.924,-44.088) 1(-6.924,-44.063) 1(-6.899,-44.113) 1(-6.873,-44.164) 1(-6.873,-44.139) 1(-6.848,-44.19) 1(-6.822,-44.24) 1(-6.822,-44.215) 1(-6.797,-44.317) 1(-6.797,-44.291) 1(-6.797,-44.266) 1(-6.772,-44.393) 1(-6.772,-44.367) 1(-6.772,-44.342) 1(-6.746,-44.494) 1(-6.746,-44.469) 1(-6.746,-44.444) 1(-6.746,-44.418) 1(-6.721,-44.647) 1(-6.721,-44.621) 1(-6.721,-44.596) 1(-6.721,-44.571) 1(-6.721,-44.545) 1(-6.721,-44.52) 1(-6.695,-46.501) 1(-6.695,-46.476) 1(-6.695,-46.45) 1(-6.695,-46.425) 1(-6.695,-46.399) 1(-6.695,-46.374) 1(-6.695,-46.349) 1(-6.695,-46.323) 1(-6.695,-46.298) 1(-6.695,-46.272) 1(-6.695,-46.247) 1(-6.695,-46.222) 1(-6.695,-46.196) 1(-6.695,-46.171) 1(-6.695,-46.145) 1(-6.695,-46.12) 1(-6.695,-46.095) 1(-6.695,-46.069) 1(-6.695,-46.044) 1(-6.695,-46.018) 1(-6.695,-45.993) 1(-6.695,-45.968) 1(-6.695,-45.942) 1(-6.695,-45.917) 1(-6.695,-45.891) 1(-6.695,-45.866) 1(-6.695,-45.841) 1(-6.695,-45.815) 1(-6.695,-45.79) 1(-6.695,-45.764) 1(-6.695,-45.739) 1(-6.695,-45.714) 1(-6.695,-45.688) 1(-6.695,-45.663) 1(-6.695,-45.637) 1(-6.695,-45.612) 1(-6.695,-45.587) 1(-6.695,-45.561) 1(-6.695,-45.536) 1(-6.695,-45.51) 1(-6.695,-45.485) 1(-6.695,-45.46) 1(-6.695,-45.434) 1(-6.695,-45.409) 1(-6.695,-45.383) 1(-6.695,-45.358) 1(-6.695,-45.333) 1(-6.695,-45.307) 1(-6.695,-45.282) 1(-6.695,-45.256) 1(-6.695,-45.231) 1(-6.695,-45.206) 1(-6.695,-45.18) 1(-6.695,-45.155) 1(-6.695,-45.129) 1(-6.695,-45.104) 1(-6.695,-45.079) 1(-6.695,-45.053) 1(-6.695,-45.028) 1(-6.695,-45.002) 1(-6.695,-44.977) 1(-6.695,-44.952) 1(-6.695,-44.926) 1(-6.695,-44.901) 1(-6.695,-44.875) 1(-6.695,-44.85) 1(-6.695,-44.825) 1(-6.695,-44.799) 1(-6.695,-44.774) 1(-6.695,-44.748) 1(-6.695,-44.723) 1(-6.695,-44.698) 1(-6.695,-44.672) 1(-6.416,-43.783) 1(-6.391,-43.859) 1(-6.391,-43.834) 1(-6.391,-43.809) 1(-6.365,-43.91) 1(-6.365,-43.885) 1(-6.34,-43.961) 1(-6.34,-43.936) 1(-6.314,-44.037) 1(-6.314,-44.012) 1(-6.314,-43.986) 1(-6.289,-44.088) 1(-6.289,-44.063) 1(-6.264,-47.72) 1(-6.264,-47.695) 1(-6.264,-47.669) 1(-6.264,-47.644) 1(-6.264,-47.619) 1(-6.264,-47.593) 1(-6.264,-47.568) 1(-6.264,-47.542) 1(-6.264,-47.517) 1(-6.264,-47.492) 1(-6.264,-47.466) 1(-6.264,-47.441) 1(-6.264,-47.415) 1(-6.264,-47.39) 1(-6.264,-47.365) 1(-6.264,-47.339) 1(-6.264,-47.314) 1(-6.264,-47.288) 1(-6.264,-47.263) 1(-6.264,-47.238) 1(-6.264,-47.212) 1(-6.264,-47.187) 1(-6.264,-47.161) 1(-6.264,-47.136) 1(-6.264,-47.111) 1(-6.264,-47.085) 1(-6.264,-44.164) 1(-6.264,-44.139) 1(-6.264,-44.113) 1(-6.238,-44.215) 1(-6.238,-44.19) 1(-6.213,-47.085) 1(-6.213,-44.291) 1(-6.213,-44.266) 1(-6.213,-44.24) 1(-6.187,-47.746) 1(-6.187,-44.342) 1(-6.187,-44.317) 1(-6.162,-47.111) 1(-6.162,-44.418) 1(-6.162,-44.393) 1(-6.162,-44.367) 1(-6.137,-44.469) 1(-6.137,-44.444) 1(-6.111,-47.136) 1(-6.111,-44.545) 1(-6.111,-44.52) 1(-6.111,-44.494) 1(-6.086,-44.596) 1(-6.086,-44.571) 1(-6.06,-44.672) 1(-6.06,-44.647) 1(-6.06,-44.621) 1(-6.035,-47.771) 1(-6.035,-44.723) 1(-6.035,-44.698) 1(-6.01,-47.161) 1(-6.01,-44.774) 1(-6.01,-44.748) 1(-5.984,-44.85) 1(-5.984,-44.825) 1(-5.984,-44.799) 1(-5.959,-44.901) 1(-5.959,-44.875) 1(-5.933,-44.977) 1(-5.933,-44.952) 1(-5.933,-44.926) 1(-5.908,-45.028) 1(-5.908,-45.002) 1(-5.883,-45.104) 1(-5.883,-45.079) 1(-5.883,-45.053) 1(-5.857,-45.155) 1(-5.857,-45.129) 1(-5.832,-45.231) 1(-5.832,-45.206) 1(-5.832,-45.18) 1(-5.806,-47.161) 1(-5.806,-45.282) 1(-5.806,-45.256) 1(-5.781,-45.358) 1(-5.781,-45.333) 1(-5.781,-45.307) 1(-5.756,-45.409) 1(-5.756,-45.383) 1(-5.73,-45.485) 1(-5.73,-45.46) 1(-5.73,-45.434) 1(-5.705,-47.136) 1(-5.705,-45.536) 1(-5.705,-45.51) 1(-5.679,-45.587) 1(-5.679,-45.561) 1(-5.654,-47.111) 1(-5.654,-45.663) 1(-5.654,-45.637) 1(-5.654,-45.612) 1(-5.629,-47.085) 1(-5.629,-45.714) 1(-5.629,-45.688) 1(-5.603,-47.06) 1(-5.603,-45.79) 1(-5.603,-45.764) 1(-5.603,-45.739) 1(-5.578,-47.771) 1(-5.578,-47.034) 1(-5.578,-45.841) 1(-5.578,-45.815) 1(-5.552,-47.009) 1(-5.552,-45.917) 1(-5.552,-45.891) 1(-5.552,-45.866) 1(-5.527,-46.984) 1(-5.527,-45.968) 1(-5.527,-45.942) 1(-5.502,-46.958) 1(-5.502,-46.933) 1(-5.502,-46.044) 1(-5.502,-46.018) 1(-5.502,-45.993) 1(-5.476,-47.746) 1(-5.476,-46.907) 1(-5.476,-46.882) 1(-5.476,-46.095) 1(-5.476,-46.069) 1(-5.476,-43.834) 1(-5.476,-43.809) 1(-5.476,-43.783) 1(-5.451,-46.857) 1(-5.451,-46.831) 1(-5.451,-46.171) 1(-5.451,-46.145) 1(-5.451,-46.12) 1(-5.451,-43.91) 1(-5.451,-43.885) 1(-5.451,-43.859) 1(-5.425,-46.806) 1(-5.425,-46.78) 1(-5.425,-46.755) 1(-5.425,-46.222) 1(-5.425,-46.196) 1(-5.425,-44.012) 1(-5.425,-43.986) 1(-5.425,-43.961) 1(-5.425,-43.936) 1(-5.4,-47.72) 1(-5.4,-46.73) 1(-5.4,-46.704) 1(-5.4,-46.298) 1(-5.4,-46.272) 1(-5.4,-46.247) 1(-5.4,-44.088) 1(-5.4,-44.063) 1(-5.4,-44.037) 1(-5.375,-46.679) 1(-5.375,-46.653) 1(-5.375,-46.349) 1(-5.375,-46.323) 1(-5.375,-44.164) 1(-5.375,-44.139) 1(-5.375,-44.113) 1(-5.349,-46.628) 1(-5.349,-46.603) 1(-5.349,-46.577) 1(-5.349,-46.425) 1(-5.349,-46.399) 1(-5.349,-46.374) 1(-5.349,-44.24) 1(-5.349,-44.215) 1(-5.349,-44.19) 1(-5.324,-47.695) 1(-5.324,-46.552) 1(-5.324,-46.526) 1(-5.324,-46.476) 1(-5.324,-46.45) 1(-5.324,-44.317) 1(-5.324,-44.291) 1(-5.324,-44.266) 1(-5.298,-46.501) 1(-5.298,-44.418) 1(-5.298,-44.393) 1(-5.298,-44.367) 1(-5.298,-44.342) 1(-5.273,-47.669) 1(-5.273,-44.494) 1(-5.273,-44.469) 1(-5.273,-44.444) 1(-5.248,-44.571) 1(-5.248,-44.545) 1(-5.248,-44.52) 1(-5.222,-47.644) 1(-5.222,-44.647) 1(-5.222,-44.621) 1(-5.222,-44.596) 1(-5.197,-47.619) 1(-5.197,-44.723) 1(-5.197,-44.698) 1(-5.197,-44.672) 1(-5.171,-44.799) 1(-5.171,-44.774) 1(-5.171,-44.748) 1(-5.146,-47.593) 1(-5.146,-44.901) 1(-5.146,-44.875) 1(-5.146,-44.85) 1(-5.146,-44.825) 1(-5.121,-47.568) 1(-5.121,-44.977) 1(-5.121,-44.952) 1(-5.121,-44.926) 1(-5.095,-47.542) 1(-5.095,-45.053) 1(-5.095,-45.028) 1(-5.095,-45.002) 1(-5.07,-45.129) 1(-5.07,-45.104) 1(-5.07,-45.079) 1(-5.044,-47.517) 1(-5.044,-45.206) 1(-5.044,-45.18) 1(-5.044,-45.155) 1(-5.019,-47.492) 1(-5.019,-45.307) 1(-5.019,-45.282) 1(-5.019,-45.256) 1(-5.019,-45.231) 1(-4.994,-47.466) 1(-4.994,-45.383) 1(-4.994,-45.358) 1(-4.994,-45.333) 1(-4.968,-47.441) 1(-4.968,-47.415) 1(-4.968,-45.46) 1(-4.968,-45.434) 1(-4.968,-45.409) 1(-4.943,-47.39) 1(-4.943,-45.536) 1(-4.943,-45.51) 1(-4.943,-45.485) 1(-4.917,-47.365) 1(-4.917,-45.663) 1(-4.917,-45.637) 1(-4.917,-45.612) 1(-4.917,-45.587) 1(-4.917,-45.561) 1(-4.892,-47.339) 1(-4.892,-45.688) 1(-4.867,-47.314) 1(-4.867,-47.288) 1(-4.867,-45.688) 1(-4.867,-45.663) 1(-4.867,-45.637) 1(-4.867,-45.612) 1(-4.841,-47.263) 1(-4.841,-45.587) 1(-4.841,-45.561) 1(-4.841,-45.536) 1(-4.816,-47.238) 1(-4.816,-45.51) 1(-4.816,-45.485) 1(-4.816,-45.46) 1(-4.816,-45.434) 1(-4.79,-47.212) 1(-4.79,-47.187) 1(-4.79,-45.409) 1(-4.79,-45.383) 1(-4.79,-45.358) 1(-4.765,-47.161) 1(-4.765,-47.136) 1(-4.765,-45.333) 1(-4.765,-45.307) 1(-4.765,-45.282) 1(-4.74,-47.111) 1(-4.74,-47.085) 1(-4.74,-45.256) 1(-4.74,-45.231) 1(-4.74,-45.206) 1(-4.714,-47.06) 1(-4.714,-45.18) 1(-4.714,-45.155) 1(-4.714,-45.129) 1(-4.689,-47.034) 1(-4.689,-47.009) 1(-4.689,-45.104) 1(-4.689,-45.079) 1(-4.689,-45.053) 1(-4.663,-46.984) 1(-4.663,-46.958) 1(-4.663,-46.933) 1(-4.663,-45.028) 1(-4.663,-45.002) 1(-4.663,-44.977) 1(-4.638,-46.907) 1(-4.638,-46.882) 1(-4.638,-44.952) 1(-4.638,-44.926) 1(-4.638,-44.901) 1(-4.613,-46.857) 1(-4.613,-46.831) 1(-4.613,-44.875) 1(-4.613,-44.85) 1(-4.613,-44.825) 1(-4.587,-46.806) 1(-4.587,-46.78) 1(-4.587,-46.755) 1(-4.587,-44.799) 1(-4.587,-44.774) 1(-4.587,-44.748) 1(-4.562,-46.73) 1(-4.562,-46.704) 1(-4.562,-44.723) 1(-4.562,-44.698) 1(-4.562,-44.672) 1(-4.536,-46.679) 1(-4.536,-46.653) 1(-4.536,-46.628) 1(-4.536,-44.647) 1(-4.536,-44.621) 1(-4.536,-44.596) 1(-4.511,-46.603) 1(-4.511,-46.577) 1(-4.511,-44.571) 1(-4.511,-44.545) 1(-4.511,-44.52) 1(-4.486,-46.552) 1(-4.486,-46.526) 1(-4.486,-46.501) 1(-4.486,-44.494) 1(-4.486,-44.469) 1(-4.486,-44.444) 1(-4.486,-44.418) 1(-4.46,-46.476) 1(-4.46,-46.45) 1(-4.46,-46.425) 1(-4.46,-44.393) 1(-4.46,-44.367) 1(-4.46,-44.342) 1(-4.435,-46.399) 1(-4.435,-46.374) 1(-4.435,-44.317) 1(-4.435,-44.291) 1(-4.435,-44.266) 1(-4.409,-46.349) 1(-4.409,-46.323) 1(-4.409,-46.298) 1(-4.409,-44.24) 1(-4.409,-44.215) 1(-4.409,-44.19) 1(-4.384,-46.272) 1(-4.384,-46.247) 1(-4.384,-46.222) 1(-4.384,-44.164) 1(-4.384,-44.139) 1(-4.384,-44.113) 1(-4.359,-46.196) 1(-4.359,-46.171) 1(-4.359,-44.088) 1(-4.359,-44.063) 1(-4.359,-44.037) 1(-4.333,-46.145) 1(-4.333,-46.12) 1(-4.333,-46.095) 1(-4.333,-44.012) 1(-4.333,-43.986) 1(-4.333,-43.961) 1(-4.308,-46.069) 1(-4.308,-46.044) 1(-4.308,-43.936) 1(-4.308,-43.91) 1(-4.308,-43.885) 1(-4.282,-46.018) 1(-4.282,-45.993) 1(-4.282,-45.968) 1(-4.282,-43.859) 1(-4.282,-43.834) 1(-4.282,-43.809) 1(-4.257,-45.942) 1(-4.257,-45.917) 1(-4.257,-45.891) 1(-4.257,-43.783) 1(-4.232,-45.866) 1(-4.232,-45.841) 1(-4.206,-45.815) 1(-4.206,-45.79) 1(-4.206,-45.764) 1(-4.181,-45.739) 1(-4.181,-45.714) 1(-4.155,-45.688) 1(-4.155,-45.663) 1(-4.155,-45.637) 1(-4.13,-45.612) 1(-4.13,-45.587) 1(-4.13,-45.561) 1(-4.105,-45.536) 1(-4.105,-45.51) 1(-4.079,-45.485) 1(-4.079,-45.46) 1(-4.079,-45.434) 1(-4.054,-45.409) 1(-4.054,-45.383) 1(-4.028,-45.358) 1(-4.028,-45.333) 1(-4.028,-45.307) 1(-4.003,-45.282) 1(-4.003,-45.256) 1(-4.003,-45.231) 1(-3.978,-45.206) 1(-3.978,-45.18) 1(-3.952,-45.155) 1(-3.952,-45.129) 1(-3.952,-45.104) 1(-3.927,-45.079) 1(-3.927,-45.053) 1(-3.901,-45.028) 1(-3.901,-45.002) 1(-3.901,-44.977) 1(-3.876,-44.952) 1(-3.876,-44.926) 1(-3.876,-44.901) 1(-3.851,-44.875) 1(-3.851,-44.85) 1(-3.825,-44.825) 1(-3.825,-44.799) 1(-3.825,-44.774) 1(-3.8,-44.748) 1(-3.8,-44.723) 1(-3.774,-44.698) 1(-3.774,-44.672) 1(-3.774,-44.647) 1(-3.749,-44.621) 1(-3.749,-44.596) 1(-3.749,-44.571) 1(-3.724,-44.545) 1(-3.724,-44.52) 1(-3.698,-44.494) 1(-3.698,-44.469) 1(-3.698,-44.444) 1(-3.673,-44.418) 1(-3.673,-44.393) 1(-3.673,-44.367) 1(-3.647,-44.342) 1(-3.647,-44.317) 1(-3.622,-44.291) 1(-3.622,-44.266) 1(-3.622,-44.24) 1(-3.597,-44.215) 1(-3.597,-44.19) 1(-3.571,-44.164) 1(-3.571,-44.139) 1(-3.571,-44.113) 1(-3.546,-44.088) 1(-3.546,-44.063) 1(-3.546,-44.037) 1(-3.52,-44.012) 1(-3.52,-43.986) 1(-3.495,-43.961) 1(-3.495,-43.936) 1(-3.495,-43.91) 1(-3.47,-43.885) 1(-3.47,-43.859) 1(-3.444,-43.834) 1(-3.444,-43.809) 1(-3.444,-43.783)

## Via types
v1: diameter 0.5, hole 0.3, Top Layer to Bottom Layer, tented both sides, 248 vias
v2: diameter 1.27, hole 0.711, Top Layer to Bottom Layer, tented both sides, 1 vias

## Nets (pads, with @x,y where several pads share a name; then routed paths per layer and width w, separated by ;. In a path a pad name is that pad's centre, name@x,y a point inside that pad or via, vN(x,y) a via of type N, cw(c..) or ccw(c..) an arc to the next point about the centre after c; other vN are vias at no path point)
+3V3: P1.1 P4.1 | length 63.4
  Top Layer w0.508: P1.1@-53.118,-1.227 -60.65,-8.759 -60.65,-40.975 -59.025,-42.6 -49.35,-42.6 -44.105,-47.845 P4.1@-44.105,-48.975
+5V: D3.1 F1.2 P1.2 P1.4 P2.1 P2.2 | length 46.3
  Top Layer w0.508: P2.2@-54.525,-11.735 P2.1@-51.985,-11.735 -48.585,-11.735 -42.962,-6.112 ; P1.4@-50.578,1.313 -50.188,1.313 -48.906,0.031 -47.517,0.031 -46.78,-0.706 -46.78,-2.295 -42.962,-6.112 ; D3.1@-30.95,-10.125 -38.95,-10.125 -42.962,-6.112
  Top Layer w0.762: P1.2@-53.118,1.313 P1.4@-50.578,1.313 ; D3.1@-30.95,-10.125 F1.2@-26.425,-10.125
+24VDC: D1.1 D2.1 U1.1 | length 15.9
  Top Layer w0.762: U1.1@-11.06,-9.475 -11.06,-12.915 -7.225,-16.75 D2.1@-4.575,-16.75 D1.1@-0.2,-16.75
C\S\: P1.24 P2.15 | length 48.1
  Top Layer w0.254: v2(-32.125,-3.775) -27.625,-3.775 -26.436,-2.586 -26.436,0.055 P1.24@-25.178,1.313
  Bottom Layer w0.254: P2.15@-51.985,-29.515 -45.99,-29.515 -32.125,-15.65 v2(-32.125,-3.775)
GND: D3.2 P1.6 P1.9 P1.14 P1.20 P1.25 P1.30 P1.34 P1.39 P2.3 P2.5 P2.6 P2.12 P2.14 P3.1 P3.3 P4.4 U1.2
  other v1: -54.812,-51.569 -51.812,-51.569 -48.812,-51.569 -45.812,-51.569 -42.812,-51.569 -39.812,-51.569 -36.812,-51.569 -33.812,-51.569 -30.812,-51.569 -27.812,-51.569 -24.812,-51.569 -21.812,-51.569 -18.812,-51.569 -15.812,-51.569 -12.812,-51.569 -9.812,-51.569 -6.812,-51.569 -3.812,-51.569 -47.312,-48.569 -32.312,-48.569 -29.312,-48.569 -26.312,-48.569 -23.312,-48.569 -20.312,-48.569 -17.312,-48.569 -14.312,-48.569 -11.312,-48.569 -8.312,-48.569 -5.312,-48.569 -60.812,-45.569 -39.812,-45.569 -36.812,-45.569 -33.812,-45.569 -30.812,-45.569 -27.812,-45.569 -24.812,-45.569 -21.812,-45.569 -18.812,-45.569 -15.812,-45.569 -12.812,-45.569 -9.812,-45.569 -6.812,-45.569 -3.812,-45.569 -0.812,-45.569 -47.312,-42.569 -41.312,-42.569 -38.312,-42.569 -35.312,-42.569 -32.312,-42.569 -29.312,-42.569 -26.312,-42.569 -23.312,-42.569 -20.312,-42.569 -17.312,-42.569 -14.312,-42.569 -11.312,-42.569 -8.312,-42.569 -5.312,-42.569 -2.312,-42.569 0.688,-42.569 -57.812,-39.569 -48.812,-39.569 -45.812,-39.569 -42.812,-39.569 -39.812,-39.569 -36.812,-39.569 -33.812,-39.569 -30.812,-39.569 -27.812,-39.569 -24.812,-39.569 -21.812,-39.569 -18.812,-39.569 -15.812,-39.569 -12.812,-39.569 -9.812,-39.569 -6.812,-39.569 -3.812,-39.569 -0.812,-39.569 -56.312,-36.569 -53.312,-36.569 -41.312,-36.569 -38.312,-36.569 -35.312,-36.569 -32.312,-36.569 -29.312,-36.569 -26.312,-36.569 -23.312,-36.569 -20.312,-36.569 -17.312,-36.569 -14.312,-36.569 -11.312,-36.569 -8.312,-36.569 -5.312,-36.569 -2.312,-36.569 0.688,-36.569 -57.812,-33.569 -48.812,-33.569 -45.812,-33.569 -36.812,-33.569 -33.812,-33.569 -30.812,-33.569 -27.812,-33.569 -24.812,-33.569 -21.812,-33.569 -18.812,-33.569 -15.812,-33.569 -12.812,-33.569 -9.812,-33.569 -6.812,-33.569 -3.812,-33.569 -0.812,-33.569 -56.312,-30.569 -35.312,-30.569 -32.312,-30.569 -29.312,-30.569 -26.312,-30.569 -23.312,-30.569 -20.312,-30.569 -17.312,-30.569 -14.312,-30.569 -11.312,-30.569 -8.312,-30.569 -5.312,-30.569 -2.312,-30.569 0.688,-30.569 -57.812,-27.569 -48.812,-27.569 -45.812,-27.569 -42.812,-27.569 -30.812,-27.569 -27.812,-27.569 -24.812,-27.569 -21.812,-27.569 -18.812,-27.569 -15.812,-27.569 -12.812,-27.569 -9.812,-27.569 -6.812,-27.569 -3.812,-27.569 -0.812,-27.569 -56.312,-24.569 -50.312,-24.569 -47.312,-24.569 -44.312,-24.569 -29.312,-24.569 -26.312,-24.569 -23.312,-24.569 -20.312,-24.569 -17.312,-24.569 -14.312,-24.569 -11.312,-24.569 -8.312,-24.569 -5.312,-24.569 -2.312,-24.569 0.688,-24.569 -57.812,-21.569 -48.812,-21.569 -45.812,-21.569 -42.812,-21.569 -39.812,-21.569 -36.812,-21.569 -24.812,-21.569 -21.812,-21.569 -18.812,-21.569 -15.812,-21.569 -12.812,-21.569 -9.812,-21.569 -6.812,-21.569 -3.812,-21.569 -0.812,-21.569 -56.312,-18.569 -53.312,-18.569 -50.312,-18.569 -47.312,-18.569 -44.312,-18.569 -41.312,-18.569 -38.312,-18.569 -23.312,-18.569 -20.312,-18.569 -17.312,-18.569 -14.312,-18.569 -11.312,-18.569 -8.312,-18.569 -5.312,-18.569 -2.312,-18.569 0.688,-18.569 -57.812,-15.569 -54.812,-15.569 -48.812,-15.569 -45.812,-15.569 -42.812,-15.569 -39.812,-15.569 -36.812,-15.569 -33.812,-15.569 -21.812,-15.569 -18.812,-15.569 -15.812,-15.569 -12.812,-15.569 -9.812,-15.569 -6.812,-15.569 -56.312,-12.569 -53.312,-12.569 -50.312,-12.569 -47.312,-12.569 -44.312,-12.569 -41.312,-12.569 -38.312,-12.569 -35.312,-12.569 -29.312,-12.569 -23.312,-12.569 -20.312,-12.569 -17.312,-12.569 -14.312,-12.569 -8.312,-12.569 -2.312,-12.569 -57.812,-9.569 -42.812,-9.569 -6.812,-9.569 -3.812,-9.569 -56.312,-6.569 -41.312,-6.569 -38.312,-6.569 -35.312,-6.569 -29.312,-6.569 -23.312,-6.569 -20.312,-6.569 -17.312,-6.569 -14.312,-6.569 -11.312,-6.569 -8.312,-6.569 -5.312,-6.569 -2.312,-6.569 -60.812,-3.569 -57.812,-3.569 -42.812,-3.569 -39.812,-3.569 -36.812,-3.569 -33.812,-3.569 -21.812,-3.569 -18.812,-3.569 -15.812,-3.569 -12.812,-3.569 -9.812,-3.569 -6.812,-3.569 -3.812,-3.569 -0.812,-3.569 -44.312,-0.569 -11.312,-0.569
MISO: P1.21 P2.17 | length 45.7
  Bottom Layer w0.254: P2.17@-51.985,-32.055 -43.805,-32.055 -27.718,-15.968 P1.21@-27.718,-1.227
MOSI: P1.19 P2.16 | length 45.8
  Bottom Layer w0.254: P2.16@-54.525,-29.515 -53.267,-30.773 -44.848,-30.773 -30.258,-16.183 P1.19@-30.258,-1.227
NetD1_2: D1.2 P3.2 | length 10.6
  Top Layer w0.762: D1.2@-0.2,-13.6 -0.2,-11.65 2.729,-8.721 2.729,-6.319 P3.2@1.265,-4.855
NetD2_2: D2.2 P3.4 | length 9.6
  Top Layer w0.762: D2.2@-4.575,-13.6 -4.575,-11.575 -3.325,-10.325 -1.665,-10.325 P3.4@1.265,-7.395
NetF1_1: F1.1 U1.3 | length 6.6
  Top Layer w0.762: F1.1@-22.425,-10.125 -21.785,-9.485 U1.3@-16.14,-9.485
RESET: P1.22 P2.19 | length 51.7
  Bottom Layer w0.254: P2.19@-51.985,-34.595 -43.945,-34.595 -26.436,-17.086 -26.436,0.031 P1.22@-27.718,1.313
SCK: P1.23 P2.18 | length 56.3
  Bottom Layer w0.254: P2.18@-54.525,-32.055 -53.267,-33.313 -53.267,-35.208 -52.598,-35.877 -51.464,-35.877 -51.441,-35.9 -42.975,-35.9 -25.178,-18.103 P1.23@-25.178,-1.227
SCL: P1.5 P4.3 | length 72.7
  Top Layer w0.254: P1.5@-48.038,-1.227 -48.038,-2.937 -46.78,-4.196 -46.78,-7.529 -49.1,-9.85 -55.7,-9.85 -59.075,-13.225 -59.075,-39.975 -57.65,-41.4 -45.375,-41.4 -39.025,-47.75 P4.3@-39.025,-48.975
SDA: P1.3 P4.2 | length 71.9
  Top Layer w0.254: P1.3@-50.578,-1.227 -50.578,-1.747 -47.575,-4.75 -47.575,-7.35 -49.525,-9.3 -56.05,-9.3 -59.675,-12.925 -59.675,-40.4 -58.167,-41.908 -46.925,-41.908 -41.565,-47.268 P4.2@-41.565,-48.975
pads on no net: P1.7 P1.8 P1.10 P1.11 P1.12 P1.13 P1.15 P1.16 P1.17 P1.18 P1.26 P1.27 P1.28 P1.29 P1.31 P1.32 P1.33 P1.35 P1.36 P1.37 P1.38 P1.40 P2.4 P2.7 P2.8 P2.9 P2.10 P2.11 P2.13 P2.20 P2.21 P2.22 P2.23 P2.24

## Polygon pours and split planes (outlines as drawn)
GND on Top Layer "TOP_GND" (solid, pour order 0): -61.5,-49.5 ccw(c-58.5,-49.5) -58.5,-52.5 0.5,-52.5 ccw(c0.5,-49.5) 3.5,-49.5 3.5,0.5 ccw(c0.5,0.5) 0.5,3.5 -58.5,3.5 ccw(c-58.5,0.5) -61.5,0.5
GND on Bottom Layer "BOT_GND" (solid, pour order 1): -61.5,-49.5 ccw(c-58.5,-49.5) -58.5,-52.5 0.5,-52.5 ccw(c0.5,-49.5) 3.5,-49.5 3.5,0.5 ccw(c0.5,0.5) 0.5,3.5 -58.5,3.5 ccw(c-58.5,0.5) -61.5,0.5

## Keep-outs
Keep-Out Layer:
  lines w0.2: -58.5,3.5 ccw(c-58.5,0.5) -61.5,0.5 -61.5,-49.5 ccw(c-58.5,-49.5) -58.5,-52.5 0.5,-52.5 ccw(c0.5,-49.5) 3.5,-49.5 ; -58.5,3.5 -58.5,3.5 ; -58.5,3.5 0.5,3.5 cw(c0.5,0.5) 3.5,0.5 3.5,-49.5 ; 3.5,-49.5 3.5,-49.5

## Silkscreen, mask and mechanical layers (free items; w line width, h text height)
Top Overlay:
  drawing of 2146 lines, arcs and shapes, not listed
  text "IRNAS.EU" at -30.275,-34.875 h5
  text "RPi PoE RAK831 HAT" at -41.725,-40.125 h5
  text "GND" at -35.55,-47.175 h1.8 r90
  text "VCC" at -43.225,-47.25 h1.8 r90
  text "SCL" at -38.15,-47.314 h1.8 r90
  text "SDA" at -40.75,-47.35 h1.8 r90
Bottom Overlay:
  drawing of 2141 lines, arcs and shapes, not listed
  text "IRNAS.EU" at -9.195,-34.278 h5
  text "RPi PoE RAK831 HAT" at 2.255,-39.528 h5
Mechanical 1:
  circle w0.1: c-51.725,-5.7 r1.525
  circle w0.1: c-51.725,-5.7 r3
  circle w0.1: c-51.725,-46.5 r1.525
  circle w0.1: c-51.725,-46.5 r3
  circle w0.1: c-58,-49 r1.525
  circle w0.1: c-58,-49 r3
  circle w0.1: c0,-49 r1.525
  circle w0.1: c0,-49 r3
  circle w0.1: c0,0 r1.525
  circle w0.1: c0,0 r3
  circle w0.1: c-58,0 r3
  circle w0.1: c-58,0 r1.525
  lines w0.1: -61.5,-49.5 ccw(c-58.5,-49.5) -58.5,-52.5 0.5,-52.5 ccw(c0.5,-49.5) 3.5,-49.5 3.5,0.5 ccw(c0.5,0.5) 0.5,3.5 -58.5,3.5 ccw(c-58.5,0.5) -61.5,0.5 -61.5,-49.5
  lines w0.2: -58,0 0,0 ; -53.118,-1.227 -53.118,0.056 -53.118,1.313
Mechanical 5:
  drawing of 470 lines, arcs and shapes, not listed
Mechanical 19:
  circle w0.25: c-95.639,-61.295 r0.125
  circle w0.25: c-96.645,-61.295 r0.125
  circle w0.25: c-96.645,-62.566 r0.125
  circle w0.25: c-99.249,-61.412 r0.125
  circle w0.25: c-98.355,-61.412 r0.125
  circle w0.25: c-98.355,-62.449 r0.125
  circle w0.25: c-96.552,-63.037 r0.125
  circle w0.25: c-96.552,-62.449 r0.125
  circle w0.25: c-98.355,-62.449 r0.125
  circle w0.25: c-94.951,-61.456 r0.125
  circle w0.25: c-94.679,-61.456 r0.125
  circle w0.25: c-94.777,-61.975 r0.125
  circle w0.25: c-94.949,-62.536 r0.125
  circle w0.25: c-94.694,-62.536 r0.125
  circle w0.25: c-94.691,-62.017 r0.125
  circle w0.25: c-94.278,-62.647 r0.125
  circle w0.25: c-94.278,-62.442 r0.125
  circle w0.25: c-94.856,-62.394 r0.125
  circle w0.25: c-93.219,-62.318 r0.125
  circle w0.25: c-93.291,-62.318 r0.125
  circle w0.25: c-93.306,-61.543 r0.125
  circle w0.25: c-93.306,-61.45 r0.125
  circle w0.25: c-93.306,-61.556 r0.125
  circle w0.25: c-94.235,-61.559 r0.125
  circle w0.25: c-94.278,-61.376 r0.125
  circle w0.25: c-94.278,-61.836 r0.125
  circle w0.25: c-94.856,-61.959 r0.125
  circle w0.25: c-98.311,-62.443 r0.125
  circle w0.25: c-98.399,-62.455 r0.125
  circle w0.25: c-98.345,-61.423 r0.125
  circle w0.25: c-98.461,-61.372 r0.125
  circle w0.25: c-96.44,-60.859 r0.125
  circle w0.25: c-96.44,-61.424 r0.125
  circle w0.25: c-98.473,-61.422 r0.125
Mechanical 22:
  region: -95.631,-61.346 -95.648,-61.346 -95.639,-61.295
  region: -95.639,-62.566 -95.648,-62.515 -95.631,-62.515
  region: -99.24,-61.463 -99.257,-61.463 -99.249,-61.412
  region: -99.249,-62.449 -99.257,-62.398 -99.24,-62.398
  region: -96.552,-63.037 -96.602,-63.046 -96.602,-63.029
  region: -98.304,-63.046 -98.355,-63.037 -98.304,-63.029
  region: -94.943,-61.507 -94.96,-61.507 -94.951,-61.456
  region: -94.951,-61.975 -94.96,-61.925 -94.943,-61.925
  region: -94.949,-62.536 -94.958,-62.485 -94.941,-62.485
  region: -94.941,-62.068 -94.958,-62.068 -94.949,-62.017
  region: -94.278,-62.647 -94.329,-62.656 -94.329,-62.639
  region: -94.805,-62.656 -94.856,-62.647 -94.805,-62.639
  region: -93.219,-62.318 -93.227,-62.267 -93.21,-62.267
  region: -93.21,-61.594 -93.227,-61.594 -93.219,-61.543
  region: -93.306,-61.45 -93.356,-61.459 -93.356,-61.442
  region: -94.184,-61.459 -94.235,-61.45 -94.184,-61.442
  region: -94.278,-61.376 -94.329,-61.384 -94.329,-61.367
  region: -94.805,-61.384 -94.856,-61.376 -94.805,-61.367
  region: -98.461,-61.372 -98.511,-61.36 -98.505,-61.344
  region: -96.44,-60.859 -96.491,-60.867 -96.491,-60.85
  region: -98.422,-60.867 -98.473,-60.859 -98.422,-60.85
  lines w0.5: -99.261,-62.449 -98.368,-62.449 ; -99.261,-61.412 -98.368,-61.412 ; -99.249,-62.398 -99.249,-62.042 ; -99.249,-61.82 -99.249,-61.463 ; -98.658,-61.871 -98.462,-61.878 ; -98.633,-61.298 -98.508,-61.352 ; -98.473,-61.41 -98.473,-60.846 ; -98.422,-60.859 -97.596,-60.859 ; -98.355,-63.05 -98.355,-62.461 ; -98.304,-63.037 -97.51,-63.037 ; -97.397,-63.037 -96.602,-63.037 ; -97.317,-60.859 -96.491,-60.859 ; -96.632,-62.566 -95.626,-62.566 ; -96.632,-61.295 -95.626,-61.295 ; -96.552,-63.05 -96.552,-62.461 ; -96.45,-61.92 -96.283,-61.858 ; -96.44,-61.411 -96.44,-60.846 ; -95.639,-62.515 -95.639,-62.063 ; -95.639,-61.798 -95.639,-61.346 ; -94.964,-61.975 -94.79,-61.975 ; -94.964,-61.456 -94.691,-61.456 ; -94.962,-62.536 -94.707,-62.536 ; -94.962,-62.017 -94.703,-62.017 ; -94.951,-61.925 -94.951,-61.856 ; -94.951,-61.576 -94.951,-61.507 ; -94.949,-62.485 -94.949,-62.416 ; -94.949,-62.137 -94.949,-62.068 ; -94.856,-62.66 -94.856,-62.406 ; -94.856,-61.947 -94.856,-61.363 ; -94.805,-62.647 -94.707,-62.647 ; -94.805,-61.376 -94.707,-61.376 ; -94.427,-62.647 -94.329,-62.647 ; -94.427,-61.376 -94.329,-61.376 ; -94.278,-62.66 -94.278,-62.455 ; -94.278,-61.823 -94.278,-61.363 ; -94.235,-61.546 -94.235,-61.438 ; -94.184,-61.45 -93.91,-61.45 ; -93.63,-61.45 -93.356,-61.45 ; -93.306,-61.543 -93.306,-61.438 ; -93.293,-61.543 -93.206,-61.543 ; -93.278,-62.318 -93.206,-62.318 ; -93.219,-62.267 -93.219,-62.063 ; -93.219,-61.799 -93.219,-61.594
  text "80.05" at -97.457,-60.891 h0.06
  text "R5*4" at -98.747,-61.281 h0.06 r336.66
  text "22.76" at -94.567,-61.407 h0.06
  text "36.59" at -93.77,-61.482 h0.06
  text "20.43" at -94.951,-61.748 h0.06 r90
  text "40.8" at -99.249,-61.962 h0.06 r90
  text "50.01" at -95.639,-61.962 h0.06 r90
  text "30.51" at -93.219,-61.963 h0.06 r90
  text "20.43" at -94.949,-62.309 h0.06 r90
  text "22.76" at -94.567,-62.679 h0.06
  text "71" at -97.453,-63.069 h0.06

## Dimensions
-61.5,0.5 to 3.5,0.5 on Mechanical 1
-58,0 to 0,0 on Mechanical 1
-58.5,3.5 to -58.5,-52.5 on Mechanical 1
